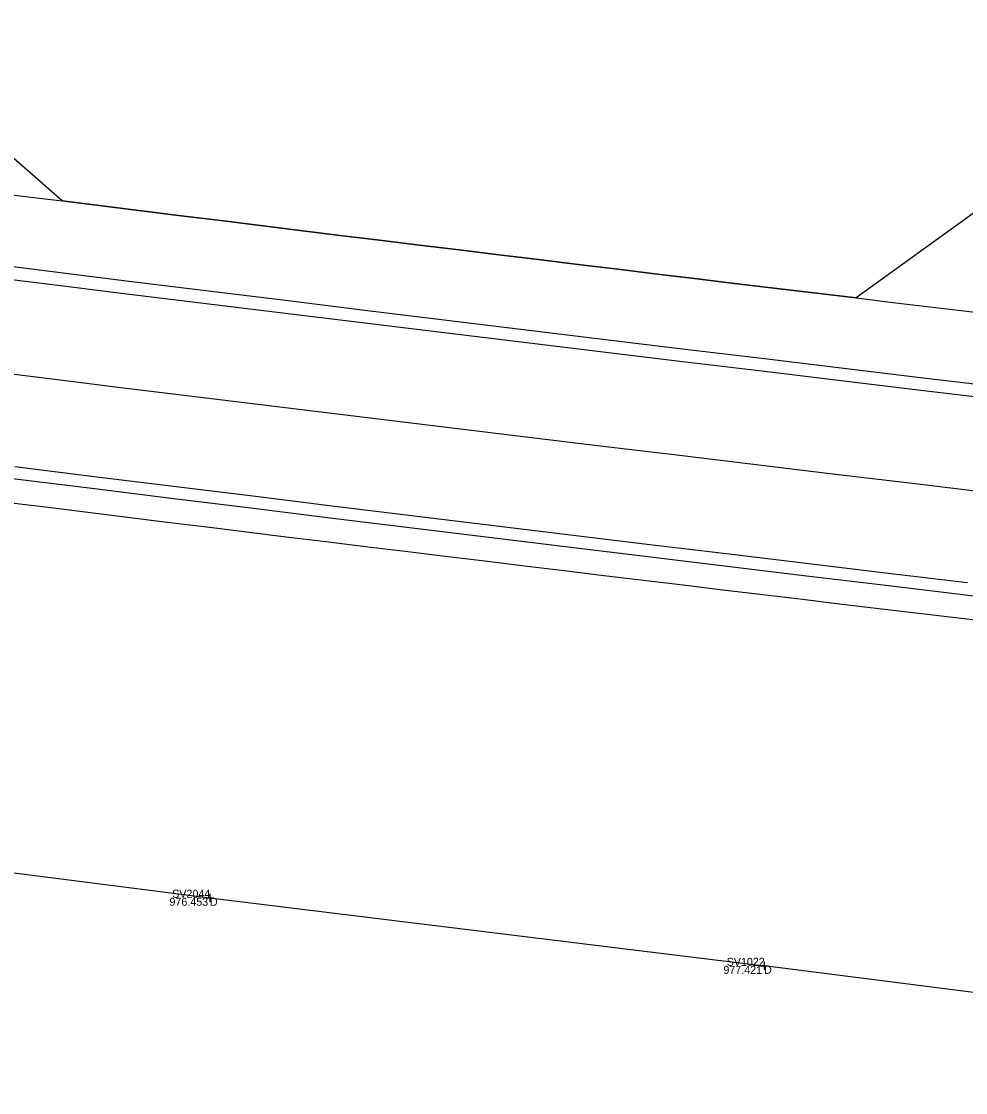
# Model space of a CAD drawing. Extents: x 2065431 to 2068157, y 709104 to 709719.
# Drawn here: x 2066854.9 to 2066972.9, y 709384.1 to 709518 of the extents above; entities that cross this region are included whole.
import ezdxf

# ---------------------------------------------------------------- set-up
doc = ezdxf.new("R2010")
doc.units = 0
for name, color, linetype in [('DT_X_Terrain_Boundary', 7, 'Continuous'), ('PM_X_Edge_Line', 7, 'Continuous'), ('PM_X_Lane_Line', 7, 'Continuous'), ('PV_X_EOP', 7, 'Continuous'), ('PV_X_Shoulder_Rumble_Strip', 7, 'Continuous'), ('RS_Raster1', 7, 'Continuous'), ('RW_X_Fee_WL', 7, 'Continuous'), ('SV_X_Mon_Cells_Found', 7, 'Continuous'), ('SV_X_Text_Elevation', 7, 'Continuous'), ('SV_X_Text_Name', 7, 'Continuous')]:
    doc.layers.add(name, color=color, linetype=linetype)

msp = doc.modelspace()

# ---------------------------------------------------------------- linework, layer by layer
at = {"layer": 'DT_X_Terrain_Boundary'}
msp.add_lwpolyline([(2066980.58, 709498.86), (2066959.21, 709483.43), (2066954.24, 709484.03), (2066949.28, 709484.63), (2066944.32, 709485.22), (2066939.35, 709485.82), (2066934.39, 709486.42), (2066929.42, 709487.02), (2066924.46, 709487.63), (2066919.5, 709488.23), (2066914.53, 709488.83), (2066909.57, 709489.44), (2066904.61, 709490.05), (2066899.64, 709490.65), (2066894.68, 709491.26), (2066889.72, 709491.87), (2066884.76, 709492.48), (2066879.79, 709493.1), (2066874.83, 709493.71), (2066869.87, 709494.32), (2066864.91, 709494.94), (2066859.95, 709495.56), (2066834.34, 709517.99)], dxfattribs=at)
at = {"layer": 'PM_X_Edge_Line'}
for points in [[(2066848.17, 709486.42), (2066858.09, 709485.19), (2066868.02, 709483.97), (2066877.94, 709482.74), (2066887.87, 709481.53), (2066897.8, 709480.31), (2066907.72, 709479.1), (2066917.65, 709477.9), (2066927.58, 709476.7), (2066937.5, 709475.5), (2066947.43, 709474.31), (2066957.36, 709473.12), (2066967.29, 709471.93), (2066977.22, 709470.75)], [(2066854.02, 709462.36), (2066863.94, 709461.13), (2066873.87, 709459.91), (2066883.79, 709458.69), (2066893.72, 709457.47), (2066903.64, 709456.26), (2066913.57, 709455.05), (2066923.5, 709453.84), (2066933.43, 709452.64), (2066943.35, 709451.45), (2066953.28, 709450.25), (2066963.21, 709449.06), (2066973.14, 709447.87)]]:
    msp.add_lwpolyline(points, dxfattribs=at)
at = {"layer": 'PM_X_Lane_Line'}
msp.add_lwpolyline([(2066847.45, 709474.7), (2066857.37, 709473.48), (2066867.3, 709472.26), (2066877.23, 709471.04), (2066887.15, 709469.83), (2066897.08, 709468.61), (2066907, 709467.41), (2066916.93, 709466.2), (2066926.86, 709465.01), (2066936.79, 709463.81), (2066946.72, 709462.62), (2066956.65, 709461.43), (2066966.58, 709460.24), (2066976.51, 709459.06)], dxfattribs=at)
at = {"layer": 'PV_X_EOP'}
for points in [[(2066850.02, 709496.79), (2066854.98, 709496.17), (2066859.95, 709495.56), (2066864.91, 709494.94), (2066869.87, 709494.32), (2066874.83, 709493.71), (2066879.79, 709493.1), (2066884.76, 709492.48), (2066889.72, 709491.87), (2066894.68, 709491.26), (2066899.64, 709490.65), (2066904.61, 709490.05), (2066909.57, 709489.44), (2066914.53, 709488.83), (2066919.5, 709488.23), (2066924.46, 709487.63), (2066929.42, 709487.02), (2066934.39, 709486.42), (2066939.35, 709485.82), (2066944.32, 709485.22), (2066949.28, 709484.63), (2066954.24, 709484.03), (2066959.21, 709483.43), (2066964.17, 709482.84), (2066969.14, 709482.24), (2066974.1, 709481.65)], [(2066853.23, 709457.89), (2066858.19, 709457.28), (2066863.15, 709456.66), (2066868.11, 709456.05), (2066873.08, 709455.43), (2066878.04, 709454.82), (2066883, 709454.21), (2066887.96, 709453.6), (2066892.93, 709452.99), (2066897.89, 709452.39), (2066902.85, 709451.78), (2066907.82, 709451.17), (2066912.78, 709450.57), (2066917.74, 709449.97), (2066922.71, 709449.37), (2066927.67, 709448.76), (2066932.63, 709448.17), (2066937.6, 709447.57), (2066942.56, 709446.97), (2066947.53, 709446.37), (2066952.49, 709445.78), (2066957.46, 709445.18), (2066962.42, 709444.59), (2066967.39, 709444), (2066972.35, 709443.41), (2066977.32, 709442.82)]]:
    msp.add_lwpolyline(points, dxfattribs=at)
at = {"layer": 'PV_X_Shoulder_Rumble_Strip'}
for points in [[(2066848.5, 709488.02), (2066858.42, 709486.79), (2066868.34, 709485.55), (2066878.27, 709484.32), (2066888.19, 709483.1), (2066898.12, 709481.88), (2066908.04, 709480.67), (2066917.97, 709479.46), (2066927.9, 709478.25), (2066937.82, 709477.05), (2066947.75, 709475.85), (2066957.68, 709474.66), (2066967.61, 709473.47), (2066977.54, 709472.28)], [(2066853.76, 709460.88), (2066863.68, 709459.65), (2066873.6, 709458.42), (2066883.53, 709457.19), (2066893.45, 709455.97), (2066903.38, 709454.76), (2066913.31, 709453.54), (2066923.23, 709452.33), (2066933.16, 709451.13), (2066943.09, 709449.93), (2066953.02, 709448.73), (2066962.94, 709447.54), (2066972.87, 709446.35), (2066982.8, 709445.17)]]:
    msp.add_lwpolyline(points, dxfattribs=at)
at = {"layer": 'RS_Raster1'}
for p, q in [((2066877.93, 709408.48), (2066878.93, 709408.48)), ((2066878.43, 709408.98), (2066878.43, 709407.98)), ((2066878.43, 709408.48), (2066878.43, 709408.48)), ((2066947.7, 709400.47), (2066947.7, 709399.47)), ((2066947.2, 709399.97), (2066948.2, 709399.97)), ((2066947.7, 709399.97), (2066947.7, 709399.97))]:
    msp.add_line(p, q, dxfattribs=at)
at = {"layer": 'RW_X_Fee_WL'}
for points in [[(2066146.22, 709516.28), (2066201.46, 709507.43), (2066256.41, 709499.89), (2066309.66, 709487.73), (2066371.95, 709478.62), (2066434.46, 709468.76), (2066488.47, 709461.11), (2066543.09, 709454.02), (2066597.26, 709445.92), (2066653.85, 709437.6), (2066711.8, 709429.8), (2066769.12, 709422.19), (2066823.53, 709415.48), (2066878.43, 709408.48), (2066947.7, 709399.97)], [(2067108.16, 709384.13), (2067055.78, 709385.5), (2066998.43, 709393.53), (2066947.7, 709399.97)]]:
    msp.add_lwpolyline(points, dxfattribs=at)

# ---------------------------------------------------------------- texts
at = {"layer": 'SV_X_Mon_Cells_Found'}
for s, p in [('SV2044', (2066873.71, 709408.48)), ('SV1022', (2066943.03, 709399.97))]:
    msp.add_text(s, height=1, dxfattribs=at).set_placement(p)
at = {"layer": 'SV_X_Text_Elevation'}
for p in [(2066878.43, 709407.48), (2066947.7, 709398.97)]:
    msp.add_text('D', height=1, dxfattribs=at).set_placement(p)
at = {"layer": 'SV_X_Text_Name'}
for s, p in [('976.453', (2066873.37, 709407.48)), ('977.421', (2066942.62, 709398.97))]:
    msp.add_text(s, height=1, dxfattribs=at).set_placement(p)

doc.saveas('drawing.dxf')
